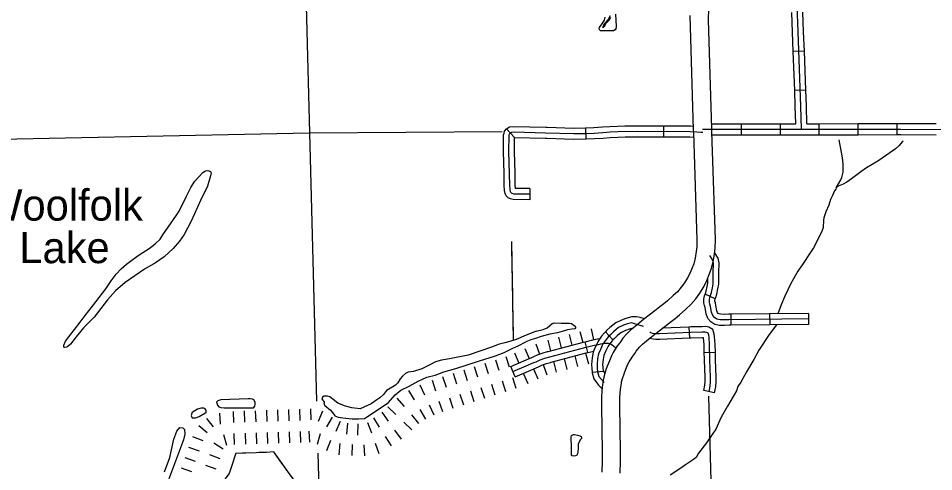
# Model space of a CAD drawing. Extents: x 1164457 to 1439835, y 1590918 to 1773502.
# Drawn here: x 1310389 to 1322808, y 1624593 to 1630737 of the extents above; entities that cross this region are included whole.
import ezdxf

# ---------------------------------------------------------------- set-up
doc = ezdxf.new("R2010")
doc.units = 0
for name, color, linetype in [('Level 10', 7, 'Continuous'), ('Level 29', 7, 'Continuous'), ('Level 32', 7, 'Continuous'), ('Level 35', 7, 'Continuous'), ('Level 43', 7, 'Continuous'), ('Level 45', 7, 'Continuous'), ('Level 5', 7, 'Continuous')]:
    doc.layers.add(name, color=color, linetype=linetype)

msp = doc.modelspace()

# ---------------------------------------------------------------- linework, layer by layer
at = {"layer": 'Level 10'}
for points in [[(1319751, 1630715), (1319764, 1631020), (1319771, 1631200), (1319797, 1631399), (1319829, 1631494), (1319838, 1631517), (1319849, 1631537), (1319863, 1631559), (1319879, 1631581), (1319903, 1631609), (1319931, 1631640), (1319981, 1631683), (1320005, 1631700), (1320018, 1631710), (1320044, 1631724), (1320096, 1631749)], [(1319499, 1630776), (1319547, 1629228), (1319550, 1629188), (1319596, 1627737), (1319594, 1627641), (1319586, 1627577), (1319573, 1627489), (1319552, 1627412), (1319531, 1627355), (1319503, 1627288), (1319470, 1627219), (1319429, 1627153), (1319384, 1627092), (1319332, 1627031), (1319276, 1626979), (1319196, 1626907), (1319148, 1626867), (1319095, 1626829), (1319027, 1626775), (1318950, 1626714), (1318873, 1626656), (1318780, 1626581), (1318692, 1626507), (1318642, 1626458), (1318592, 1626402), (1318568, 1626367), (1318550, 1626341), (1318520, 1626301), (1318489, 1626254), (1318462, 1626207), (1318436, 1626163), (1318408, 1626095), (1318384, 1626034), (1318367, 1625987), (1318353, 1625943), (1318332, 1625872), (1318324, 1625833), (1318320, 1625799), (1318317, 1625780), (1318306, 1625686), (1318301, 1625601), (1318302, 1625484), (1318309, 1624863), (1318309, 1624789), (1318309, 1624698), (1318306, 1624623), (1318305, 1624586)], [(1318555, 1624573), (1318556, 1624614), (1318559, 1624694), (1318559, 1624790), (1318559, 1624865), (1318552, 1625487), (1318551, 1625594), (1318555, 1625664), (1318565, 1625745), (1318568, 1625763), (1318571, 1625793), (1318575, 1625811), (1318592, 1625870), (1318604, 1625906), (1318618, 1625945), (1318640, 1626003), (1318660, 1626050), (1318678, 1626080), (1318702, 1626123), (1318726, 1626159), (1318752, 1626195), (1318774, 1626225), (1318790, 1626249), (1318821, 1626284), (1318859, 1626321), (1318939, 1626388), (1319027, 1626459), (1319103, 1626517), (1319182, 1626579), (1319246, 1626629), (1319302, 1626670), (1319360, 1626718), (1319444, 1626794), (1319514, 1626858), (1319580, 1626937), (1319636, 1627012), (1319690, 1627098), (1319732, 1627186), (1319764, 1627265), (1319790, 1627336), (1319818, 1627438), (1319834, 1627542), (1319844, 1627622), (1319846, 1627739), (1319799, 1629199), (1319797, 1629239), (1319751, 1630715)]]:
    msp.add_lwpolyline(points, dxfattribs=at)
at = {"layer": 'Level 29'}
for p, q in [((1317718, 1626415), (1317756, 1626270)), ((1317863, 1626453), (1317901, 1626308)), ((1318008, 1626491), (1318046, 1626346)), ((1318008, 1626491), (1318046, 1626346)), ((1318163, 1626528), (1318195, 1626381)), ((1317411, 1626328), (1317461, 1626187)), ((1317573, 1626377), (1317611, 1626232)), ((1317573, 1626377), (1317611, 1626232)), ((1317123, 1626203), (1317182, 1626066)), ((1317123, 1626203), (1317182, 1626066)), ((1317260, 1626262), (1317320, 1626125)), ((1317939, 1626163), (1317978, 1626018)), ((1318085, 1626201), (1318123, 1626056)), ((1318085, 1626201), (1318123, 1626056)), ((1316719, 1626065), (1316764, 1625922)), ((1316719, 1626065), (1316764, 1625922)), ((1316862, 1626110), (1316907, 1625967)), ((1317005, 1626155), (1317050, 1626012)), ((1317512, 1626046), (1317562, 1625904)), ((1317649, 1626086), (1317687, 1625941)), ((1317649, 1626086), (1317687, 1625941)), ((1317794, 1626125), (1317833, 1625980)), ((1316289, 1625927), (1316335, 1625785)), ((1316289, 1625927), (1316335, 1625785)), ((1316432, 1625973), (1316478, 1625831)), ((1316575, 1626019), (1316621, 1625877)), ((1317241, 1625928), (1317300, 1625790)), ((1317241, 1625928), (1317300, 1625790)), ((1317379, 1625987), (1317439, 1625850)), ((1316002, 1625834), (1316049, 1625691)), ((1316146, 1625882), (1316192, 1625739)), ((1316952, 1625824), (1316997, 1625681)), ((1317095, 1625869), (1317140, 1625726)), ((1315684, 1625695), (1315760, 1625566)), ((1315839, 1625772), (1315901, 1625636)), ((1315839, 1625772), (1315901, 1625636)), ((1316524, 1625688), (1316570, 1625545)), ((1316666, 1625734), (1316712, 1625591)), ((1316809, 1625779), (1316854, 1625636)), ((1316809, 1625779), (1316854, 1625636)), ((1315527, 1625591), (1315625, 1625477)), ((1316096, 1625549), (1316144, 1625407)), ((1316238, 1625596), (1316284, 1625453)), ((1316381, 1625642), (1316427, 1625499)), ((1316381, 1625642), (1316427, 1625499)), ((1313455, 1625416), (1313460, 1625266)), ((1313455, 1625416), (1313460, 1625266)), ((1313605, 1625420), (1313610, 1625270)), ((1313755, 1625425), (1313760, 1625275)), ((1313905, 1625430), (1313910, 1625280)), ((1313905, 1625430), (1313910, 1625280)), ((1314055, 1625434), (1314060, 1625284)), ((1314205, 1625439), (1314210, 1625289)), ((1314355, 1625444), (1314360, 1625294)), ((1315402, 1625472), (1315511, 1625368)), ((1315402, 1625472), (1315511, 1625368)), ((1315836, 1625437), (1315912, 1625307)), ((1315964, 1625500), (1316026, 1625363)), ((1315964, 1625500), (1316026, 1625363)), ((1312941, 1625316), (1313035, 1625199)), ((1313118, 1625387), (1313126, 1625237)), ((1313305, 1625411), (1313310, 1625261)), ((1314516, 1625413), (1314459, 1625274)), ((1314647, 1625331), (1314571, 1625202)), ((1315207, 1625325), (1315287, 1625198)), ((1315320, 1625401), (1315408, 1625280)), ((1315722, 1625363), (1315819, 1625248)), ((1312837, 1625220), (1312953, 1625125)), ((1314758, 1625272), (1314695, 1625136)), ((1314855, 1625250), (1314842, 1625100)), ((1314995, 1625240), (1314989, 1625090)), ((1315128, 1625262), (1315179, 1625121)), ((1315128, 1625262), (1315179, 1625121)), ((1315619, 1625264), (1315728, 1625161)), ((1315619, 1625264), (1315728, 1625161)), ((1312751, 1625068), (1312892, 1625016)), ((1313171, 1625096), (1313213, 1624952)), ((1313315, 1625111), (1313320, 1624961)), ((1313465, 1625116), (1313470, 1624966)), ((1313465, 1625116), (1313470, 1624966)), ((1313615, 1625120), (1313619, 1624970)), ((1313765, 1625125), (1313769, 1624975)), ((1313915, 1625130), (1313919, 1624980)), ((1313915, 1625130), (1313919, 1624980)), ((1314065, 1625135), (1314069, 1624985)), ((1314214, 1625139), (1314219, 1624989)), ((1314333, 1625142), (1314338, 1624992)), ((1314486, 1625105), (1314445, 1624961)), ((1315368, 1625072), (1315448, 1624945)), ((1315495, 1625158), (1315583, 1625036)), ((1312700, 1624927), (1312841, 1624875)), ((1313042, 1624984), (1313168, 1624903)), ((1314627, 1625015), (1314570, 1624876)), ((1314751, 1624973), (1314739, 1624823)), ((1314751, 1624973), (1314739, 1624823)), ((1314921, 1624961), (1314915, 1624811)), ((1315078, 1624957), (1315086, 1624807)), ((1315229, 1624979), (1315279, 1624838)), ((1315229, 1624979), (1315279, 1624838)), ((1312982, 1624824), (1313123, 1624773)), ((1312649, 1624786), (1312789, 1624735)), ((1312649, 1624786), (1312789, 1624735)), ((1312930, 1624683), (1313071, 1624632)), ((1312930, 1624683), (1313071, 1624632)), ((1312597, 1624645), (1312738, 1624594))]:
    msp.add_line(p, q, dxfattribs=at)
at = {"layer": 'Level 32'}
for p, q in [((1321054, 1630292), (1320904, 1630286)), ((1321073, 1629764), (1320924, 1629758)), ((1320200, 1629159), (1320200, 1629309)), ((1320728, 1629159), (1320728, 1629309)), ((1321256, 1629159), (1321256, 1629309)), ((1321784, 1629160), (1321784, 1629310)), ((1322312, 1629162), (1322312, 1629312)), ((1319842, 1626934), (1319706, 1626997)), ((1320054, 1626729), (1320056, 1626579)), ((1320582, 1626734), (1320584, 1626584)), ((1321110, 1626739), (1321112, 1626589)), ((1319488, 1626553), (1319494, 1626403)), ((1318354, 1626489), (1318457, 1626380)), ((1319846, 1626208), (1319696, 1626203)), ((1318174, 1625943), (1318323, 1625957)), ((1319835, 1625664), (1319689, 1625695))]:
    msp.add_line(p, q, dxfattribs=at)
for points in [[(1321015, 1629234), (1321006, 1629548), (1320969, 1630553), (1320944, 1631279), (1320937, 1631479), (1320937, 1631589), (1320916, 1631891)], [(1320904, 1630286), (1320894, 1630551), (1320885, 1630814)], [(1321054, 1630292), (1321044, 1630556), (1321035, 1630819)], [(1320924, 1629758), (1320904, 1630286)], [(1321073, 1629764), (1321054, 1630292)], [(1321088, 1629309), (1321081, 1629551), (1321073, 1629764)], [(1320938, 1629309), (1320931, 1629546), (1320924, 1629758)], [(1319795, 1629309), (1320200, 1629309)], [(1320200, 1629309), (1320728, 1629309)], [(1320728, 1629309), (1320938, 1629309)], [(1321088, 1629309), (1321256, 1629309)], [(1321256, 1629309), (1321784, 1629310)], [(1321784, 1629310), (1322312, 1629312)], [(1322312, 1629312), (1322362, 1629312), (1322841, 1629310)], [(1319672, 1629234), (1321015, 1629234), (1322362, 1629237), (1323701, 1629231), (1324513, 1629232), (1325043, 1629234)], [(1319801, 1629159), (1320200, 1629159)], [(1320200, 1629159), (1320728, 1629159)], [(1320728, 1629159), (1321015, 1629159), (1321256, 1629159)], [(1321256, 1629159), (1321784, 1629160)], [(1321784, 1629160), (1322312, 1629162)], [(1322312, 1629162), (1322362, 1629162), (1322840, 1629160)], [(1319862, 1627523), (1319836, 1627563)], [(1319842, 1626934), (1319852, 1626954), (1319866, 1627001), (1319881, 1627072), (1319892, 1627133), (1319892, 1627222), (1319892, 1627287), (1319896, 1627423), (1319883, 1627489), (1319836, 1627563)], [(1321111, 1626664), (1320031, 1626653), (1319969, 1626649), (1319911, 1626651), (1319868, 1626660), (1319835, 1626681), (1319810, 1626711), (1319793, 1626754), (1319780, 1626831), (1319773, 1626863), (1319766, 1626892), (1319765, 1626926), (1319770, 1626955), (1319782, 1626981), (1319794, 1627020), (1319807, 1627086), (1319817, 1627140), (1319817, 1627222), (1319817, 1627289), (1319821, 1627417), (1319812, 1627461), (1319773, 1627523)], [(1319706, 1626997), (1319711, 1627008), (1319721, 1627039), (1319733, 1627101), (1319742, 1627147), (1319742, 1627207)], [(1320056, 1626579), (1320034, 1626578), (1319970, 1626574), (1319902, 1626576), (1319839, 1626590), (1319786, 1626624), (1319745, 1626671), (1319720, 1626734), (1319707, 1626817), (1319700, 1626845), (1319691, 1626881), (1319690, 1626931), (1319697, 1626977), (1319706, 1626997)], [(1320054, 1626729), (1320029, 1626728), (1319967, 1626724), (1319920, 1626726), (1319897, 1626731), (1319885, 1626739), (1319875, 1626750), (1319865, 1626774), (1319854, 1626845), (1319846, 1626880), (1319841, 1626902), (1319840, 1626921), (1319842, 1626933), (1319842, 1626934)], [(1318884, 1626664), (1318827, 1626684), (1318778, 1626692), (1318714, 1626690), (1318631, 1626668), (1318571, 1626647), (1318494, 1626610), (1318453, 1626579), (1318415, 1626545), (1318371, 1626505), (1318354, 1626489)], [(1320582, 1626734), (1320054, 1626729)], [(1321110, 1626739), (1320582, 1626734)], [(1318871, 1626561), (1318749, 1626598), (1318711, 1626612), (1318654, 1626596), (1318600, 1626577), (1318533, 1626546), (1318501, 1626522), (1318465, 1626490), (1318422, 1626450), (1318395, 1626424), (1318363, 1626385), (1318338, 1626349), (1318329, 1626335), (1318321, 1626324), (1318300, 1626281), (1318286, 1626249), (1318262, 1626189), (1318247, 1626125), (1318242, 1626046), (1318244, 1625998), (1318249, 1625947), (1318266, 1625885), (1318336, 1625802)], [(1318731, 1626540), (1318676, 1626524), (1318628, 1626508), (1318572, 1626481), (1318548, 1626464), (1318515, 1626434), (1318473, 1626395), (1318457, 1626380)], [(1319488, 1626553), (1319130, 1626538)], [(1319846, 1626208), (1319843, 1626319), (1319835, 1626423), (1319831, 1626459), (1319813, 1626522), (1319757, 1626552), (1319712, 1626559), (1319665, 1626558), (1319512, 1626554), (1319488, 1626553)], [(1320584, 1626584), (1320056, 1626579)], [(1321112, 1626589), (1320584, 1626584)], [(1318354, 1626489), (1318340, 1626476), (1318303, 1626430), (1318276, 1626391), (1318267, 1626377), (1318256, 1626362), (1318232, 1626313), (1318217, 1626279), (1318190, 1626211), (1318173, 1626136), (1318167, 1626046), (1318169, 1625992), (1318174, 1625943)], [(1319762, 1625680), (1319777, 1625754), (1319782, 1625813), (1319782, 1625887), (1319778, 1625976), (1319773, 1626123), (1319768, 1626315), (1319760, 1626416), (1319757, 1626445), (1319750, 1626470), (1319732, 1626480), (1319707, 1626484), (1319667, 1626483), (1319515, 1626479), (1319090, 1626461), (1319039, 1626461), (1319014, 1626462), (1318992, 1626466), (1318973, 1626473), (1318959, 1626489)], [(1319696, 1626203), (1319693, 1626311), (1319685, 1626409), (1319669, 1626408), (1319517, 1626404), (1319494, 1626403)], [(1318457, 1626380), (1318450, 1626373), (1318423, 1626340), (1318400, 1626307), (1318390, 1626292), (1318386, 1626286), (1318368, 1626249), (1318355, 1626220), (1318334, 1626167), (1318322, 1626114), (1318317, 1626045), (1318319, 1626003), (1318323, 1625957)], [(1319494, 1626403), (1319092, 1626386), (1319037, 1626386), (1319006, 1626387), (1318950, 1626397)], [(1319689, 1625695), (1319703, 1625764), (1319707, 1625816), (1319707, 1625886), (1319703, 1625973), (1319698, 1626121), (1319696, 1626203)], [(1319835, 1625664), (1319852, 1625743), (1319857, 1625810), (1319857, 1625889), (1319853, 1625979), (1319848, 1626125), (1319846, 1626208)], [(1318174, 1625943), (1318175, 1625933), (1318198, 1625850), (1318259, 1625765), (1318310, 1625716)], [(1318323, 1625960), (1318346, 1625922)]]:
    msp.add_lwpolyline(points, dxfattribs=at)
at = {"layer": 'Level 35'}
for points in [[(1318491, 1630795), (1318500, 1630624), (1318498, 1630595), (1318487, 1630580), (1318463, 1630569), (1318315, 1630567), (1318290, 1630569), (1318280, 1630576), (1318271, 1630593), (1318273, 1630613), (1318314, 1630670), (1318344, 1630713)], [(1318418, 1630770), (1318390, 1630723), (1318344, 1630666), (1318327, 1630642), (1318318, 1630618), (1318318, 1630611), (1318320, 1630610), (1318326, 1630615), (1318345, 1630637), (1318367, 1630672), (1318404, 1630710), (1318428, 1630754)], [(1318344, 1630713), (1318352, 1630751)], [(1322392, 1629078), (1322386, 1629070), (1322335, 1629008), (1322290, 1628968), (1322245, 1628936), (1322167, 1628883), (1322052, 1628799), (1321897, 1628710), (1321822, 1628658), (1321695, 1628562), (1321632, 1628516), (1321581, 1628489), (1321513, 1628461), (1321487, 1628442), (1321479, 1628422), (1321464, 1628399), (1321436, 1628335), (1321407, 1628280), (1321384, 1628206), (1321346, 1628116), (1321316, 1628033), (1321312, 1628002), (1321313, 1627970), (1321311, 1627935), (1321308, 1627903), (1321290, 1627849), (1321177, 1627625), (1321122, 1627546), (1321036, 1627414), (1320963, 1627311), (1320872, 1627145), (1320790, 1626971), (1320737, 1626855), (1320694, 1626732)], [(1321487, 1628442), (1321547, 1628548), (1321560, 1628582), (1321578, 1628650), (1321581, 1628700), (1321580, 1628752), (1321577, 1628811), (1321567, 1628875), (1321525, 1629090)], [(1312667, 1628318), (1312728, 1628446), (1312783, 1628529), (1312893, 1628647), (1312931, 1628668), (1312962, 1628676), (1312998, 1628662), (1313008, 1628641), (1312998, 1628602), (1312957, 1628464), (1312863, 1628268), (1312779, 1628086), (1312728, 1627978), (1312641, 1627809), (1312577, 1627716), (1312489, 1627616), (1312369, 1627505), (1312249, 1627424), (1312102, 1627336), (1311838, 1627155), (1311710, 1627042), (1311598, 1626924), (1311418, 1626687), (1311276, 1626541), (1311176, 1626422), (1311097, 1626321), (1311063, 1626288), (1311047, 1626279), (1311022, 1626276), (1311006, 1626282), (1311005, 1626309), (1311030, 1626364), (1311076, 1626422), (1311227, 1626619), (1311296, 1626710), (1311397, 1626836), (1311575, 1627069), (1311651, 1627179), (1311719, 1627270), (1311786, 1627340), (1311856, 1627404), (1311947, 1627474), (1312028, 1627533), (1312164, 1627618), (1312245, 1627681), (1312315, 1627745), (1312350, 1627802), (1312424, 1627908), (1312537, 1628069), (1312572, 1628125)], [(1312572, 1628125), (1312667, 1628318)], [(1317416, 1626497), (1317509, 1626520), (1317563, 1626544), (1317600, 1626576), (1317632, 1626602), (1317659, 1626609), (1317755, 1626605), (1317831, 1626606), (1317866, 1626608), (1317895, 1626602), (1317943, 1626567), (1317950, 1626552), (1317950, 1626542), (1317939, 1626531), (1317901, 1626525), (1317841, 1626515), (1317813, 1626506), (1317770, 1626491), (1317704, 1626477), (1317601, 1626456), (1317485, 1626426), (1317408, 1626400), (1317344, 1626379), (1317273, 1626351)], [(1320674, 1626585), (1320578, 1626453), (1320438, 1626238), (1320370, 1626115), (1320267, 1625945), (1320192, 1625808), (1320153, 1625749), (1320131, 1625688), (1320009, 1625483), (1319923, 1625330), (1319854, 1625169), (1319805, 1625097), (1319728, 1624986), (1319618, 1624843), (1319585, 1624785), (1319550, 1624758), (1319442, 1624687), (1319378, 1624640), (1319234, 1624546)], [(1317416, 1626497), (1317406, 1626494), (1317280, 1626444), (1317146, 1626386), (1317072, 1626363), (1316989, 1626341), (1316901, 1626316), (1316823, 1626286), (1316493, 1626172), (1316238, 1626124), (1316130, 1626104), (1316049, 1626080), (1315973, 1626043), (1315864, 1625986), (1315749, 1625950), (1315677, 1625943), (1315643, 1625925), (1315600, 1625886), (1315568, 1625850), (1315540, 1625799), (1315506, 1625767), (1315469, 1625745), (1315384, 1625694), (1315345, 1625637), (1315293, 1625594), (1315255, 1625569), (1315175, 1625513), (1315027, 1625446)], [(1315088, 1625314), (1315125, 1625339), (1315231, 1625408), (1315412, 1625533), (1315503, 1625634), (1315579, 1625696), (1315691, 1625751), (1315812, 1625819), (1315930, 1625873), (1316043, 1625902), (1316164, 1625948), (1316324, 1625991), (1316647, 1626094), (1316864, 1626164), (1316983, 1626207), (1317099, 1626268), (1317171, 1626297), (1317273, 1626351)], [(1313139, 1625565), (1313094, 1625553), (1313079, 1625534), (1313081, 1625523), (1313090, 1625495), (1313111, 1625473), (1313138, 1625462), (1313182, 1625457), (1313580, 1625460), (1313600, 1625479), (1313605, 1625509), (1313601, 1625537), (1313585, 1625565), (1313565, 1625576), (1313536, 1625579), (1313506, 1625579)], [(1313506, 1625579), (1313139, 1625565)], [(1315027, 1625446), (1314915, 1625457), (1314829, 1625479), (1314726, 1625523), (1314659, 1625570), (1314618, 1625607), (1314586, 1625618), (1314541, 1625616), (1314518, 1625603), (1314509, 1625581), (1314537, 1625536), (1314537, 1625520), (1314533, 1625508), (1314546, 1625488), (1314576, 1625468), (1314620, 1625431), (1314653, 1625395), (1314685, 1625351), (1314730, 1625332), (1314790, 1625321), (1314921, 1625308), (1315005, 1625308), (1315088, 1625314)], [(1312822, 1625442), (1312782, 1625420), (1312761, 1625405), (1312744, 1625389), (1312738, 1625370), (1312736, 1625355), (1312739, 1625341), (1312747, 1625325), (1312770, 1625321), (1312792, 1625325), (1312843, 1625342), (1312919, 1625385), (1312936, 1625402), (1312940, 1625417), (1312934, 1625432), (1312925, 1625443), (1312907, 1625453), (1312891, 1625456), (1312869, 1625456)], [(1312869, 1625456), (1312822, 1625442)], [(1312373, 1624591), (1312444, 1624784), (1312467, 1624889), (1312500, 1625035), (1312538, 1625144), (1312581, 1625191), (1312622, 1625187), (1312643, 1625165), (1312648, 1625101), (1312630, 1625023), (1312426, 1624485)], [(1317895, 1624958), (1317892, 1625024), (1317892, 1625066), (1317896, 1625082), (1317911, 1625094), (1317921, 1625099), (1317934, 1625099), (1317975, 1625088), (1318006, 1625081), (1318024, 1625070), (1318032, 1625059), (1318030, 1625043), (1318018, 1625029), (1318000, 1624998), (1317987, 1624967), (1317986, 1624947)], [(1317986, 1624947), (1317984, 1624909), (1317982, 1624862), (1317978, 1624835), (1317966, 1624816), (1317950, 1624807), (1317923, 1624803), (1317905, 1624809), (1317895, 1624820), (1317894, 1624835), (1317894, 1624871), (1317895, 1624958)]]:
    msp.add_lwpolyline(points, dxfattribs=at)
at = {"layer": 'Level 43'}
for points in [[(1317079, 1627713), (1317103, 1626373)], [(1317079, 1627713), (1317082, 1627515)], [(1317085, 1627383), (1317092, 1626987)], [(1317094, 1626855), (1317102, 1626459)], [(1313850, 1624861), (1313756, 1624855), (1313336, 1624841), (1313334, 1624832), (1313288, 1624677), (1313250, 1624570), (1313204, 1624510), (1313164, 1624435), (1312814, 1623490), (1312804, 1623468), (1312800, 1623451), (1312807, 1623438), (1312957, 1623160), (1312988, 1623076), (1313013, 1623003), (1313043, 1622906), (1313098, 1622495)], [(1313520, 1624847), (1313336, 1624841), (1313334, 1624832), (1313288, 1624677), (1313274, 1624638)], [(1313850, 1624861), (1313756, 1624855), (1313652, 1624851)], [(1313850, 1624861), (1314085, 1624533), (1314250, 1624324), (1314623, 1623826), (1314761, 1623642), (1314914, 1623443), (1315023, 1623293), (1315077, 1623212), (1315112, 1623145), (1315148, 1623049), (1315172, 1622949), (1315184, 1622856), (1315184, 1622679), (1315191, 1622526), (1315191, 1622375), (1315209, 1621956)], [(1313850, 1624861), (1313965, 1624700)]]:
    msp.add_lwpolyline(points, dxfattribs=at)
at = {"layer": 'Level 45'}
for p, q in [((1319147, 1629131), (1319147, 1629281)), ((1317123, 1629123), (1317013, 1629239)), ((1318094, 1629103), (1318089, 1629253)), ((1317331, 1628429), (1317330, 1628279)), ((1318116, 1626209), (1318081, 1626354)), ((1317129, 1625880), (1317070, 1626018))]:
    msp.add_line(p, q, dxfattribs=at)
for points in [[(1316980, 1629182), (1316986, 1629207), (1317013, 1629239), (1317053, 1629267), (1317113, 1629273), (1317547, 1629261), (1317566, 1629261)], [(1318089, 1629253), (1318197, 1629257), (1318313, 1629265), (1318413, 1629273), (1318519, 1629277), (1318617, 1629279)], [(1318617, 1629279), (1318786, 1629282), (1319147, 1629281)], [(1319147, 1629281), (1319507, 1629280), (1319546, 1629277)], [(1316979, 1628634), (1316971, 1628933), (1316973, 1629157), (1316980, 1629182)], [(1317331, 1628354), (1317110, 1628356), (1317091, 1628361), (1317079, 1628367), (1317070, 1628376), (1317065, 1628385), (1317061, 1628411), (1317057, 1628478), (1317046, 1628934), (1317048, 1629147), (1317054, 1629172), (1317065, 1629184), (1317080, 1629195), (1317115, 1629198), (1317544, 1629186), (1317924, 1629175), (1318088, 1629178), (1318201, 1629182), (1318319, 1629190), (1318417, 1629198), (1318521, 1629202), (1318786, 1629207), (1319504, 1629205), (1319594, 1629198), (1319648, 1629194), (1319675, 1629194)], [(1317566, 1629261), (1317924, 1629250), (1318085, 1629253), (1318089, 1629253)], [(1317129, 1628638), (1317121, 1628934), (1317123, 1629123)], [(1317123, 1629123), (1317542, 1629111), (1317562, 1629111)], [(1317562, 1629111), (1317923, 1629100), (1318090, 1629103), (1318094, 1629103)], [(1318094, 1629103), (1318205, 1629107), (1318324, 1629115), (1318421, 1629123), (1318523, 1629127), (1318621, 1629129)], [(1318621, 1629129), (1318787, 1629132), (1319147, 1629131)], [(1319147, 1629131), (1319501, 1629130), (1319552, 1629126)], [(1317330, 1628279), (1317101, 1628281), (1317065, 1628290), (1317035, 1628305), (1317009, 1628330), (1316993, 1628361), (1316986, 1628402), (1316982, 1628476), (1316979, 1628634)], [(1317331, 1628429), (1317135, 1628431), (1317132, 1628481), (1317129, 1628638)], [(1317100, 1625949), (1317280, 1626026), (1317385, 1626072), (1317414, 1626083), (1317470, 1626110), (1317532, 1626133), (1317599, 1626151), (1318074, 1626276), (1318201, 1626306), (1318261, 1626319), (1318292, 1626325), (1318330, 1626333), (1318369, 1626335), (1318391, 1626335), (1318423, 1626327), (1318448, 1626314), (1318491, 1626278)], [(1317568, 1626220), (1317580, 1626223), (1318056, 1626348), (1318081, 1626354)], [(1318081, 1626354), (1318184, 1626379), (1318246, 1626393), (1318282, 1626399)], [(1317070, 1626018), (1317250, 1626095), (1317357, 1626141), (1317384, 1626152), (1317441, 1626180), (1317509, 1626204), (1317568, 1626220)], [(1317608, 1626075), (1317618, 1626078), (1318092, 1626203), (1318116, 1626209)], [(1318116, 1626209), (1318197, 1626228)], [(1317129, 1625880), (1317309, 1625957), (1317414, 1626002), (1317445, 1626015), (1317499, 1626041), (1317554, 1626061), (1317608, 1626075)]]:
    msp.add_lwpolyline(points, dxfattribs=at)
at = {"layer": 'Level 5'}
for points in [[(1314277, 1631602), (1314340, 1629183)], [(1309039, 1629075), (1314340, 1629183)], [(1314340, 1629183), (1316952, 1629202)], [(1314340, 1629183), (1314435, 1625550)], [(1319755, 1625618), (1319797, 1623981)], [(1314453, 1624842), (1314478, 1623879)]]:
    msp.add_lwpolyline(points, dxfattribs=at)

# ---------------------------------------------------------------- texts
at = {"layer": 'Level 35'}
for s, p in [('Woolfolk', (1309913, 1627996)), ('Lake', (1310404, 1627419))]:
    msp.add_text(s, height=422.4, dxfattribs=at).set_placement(p)

doc.saveas('drawing.dxf')
